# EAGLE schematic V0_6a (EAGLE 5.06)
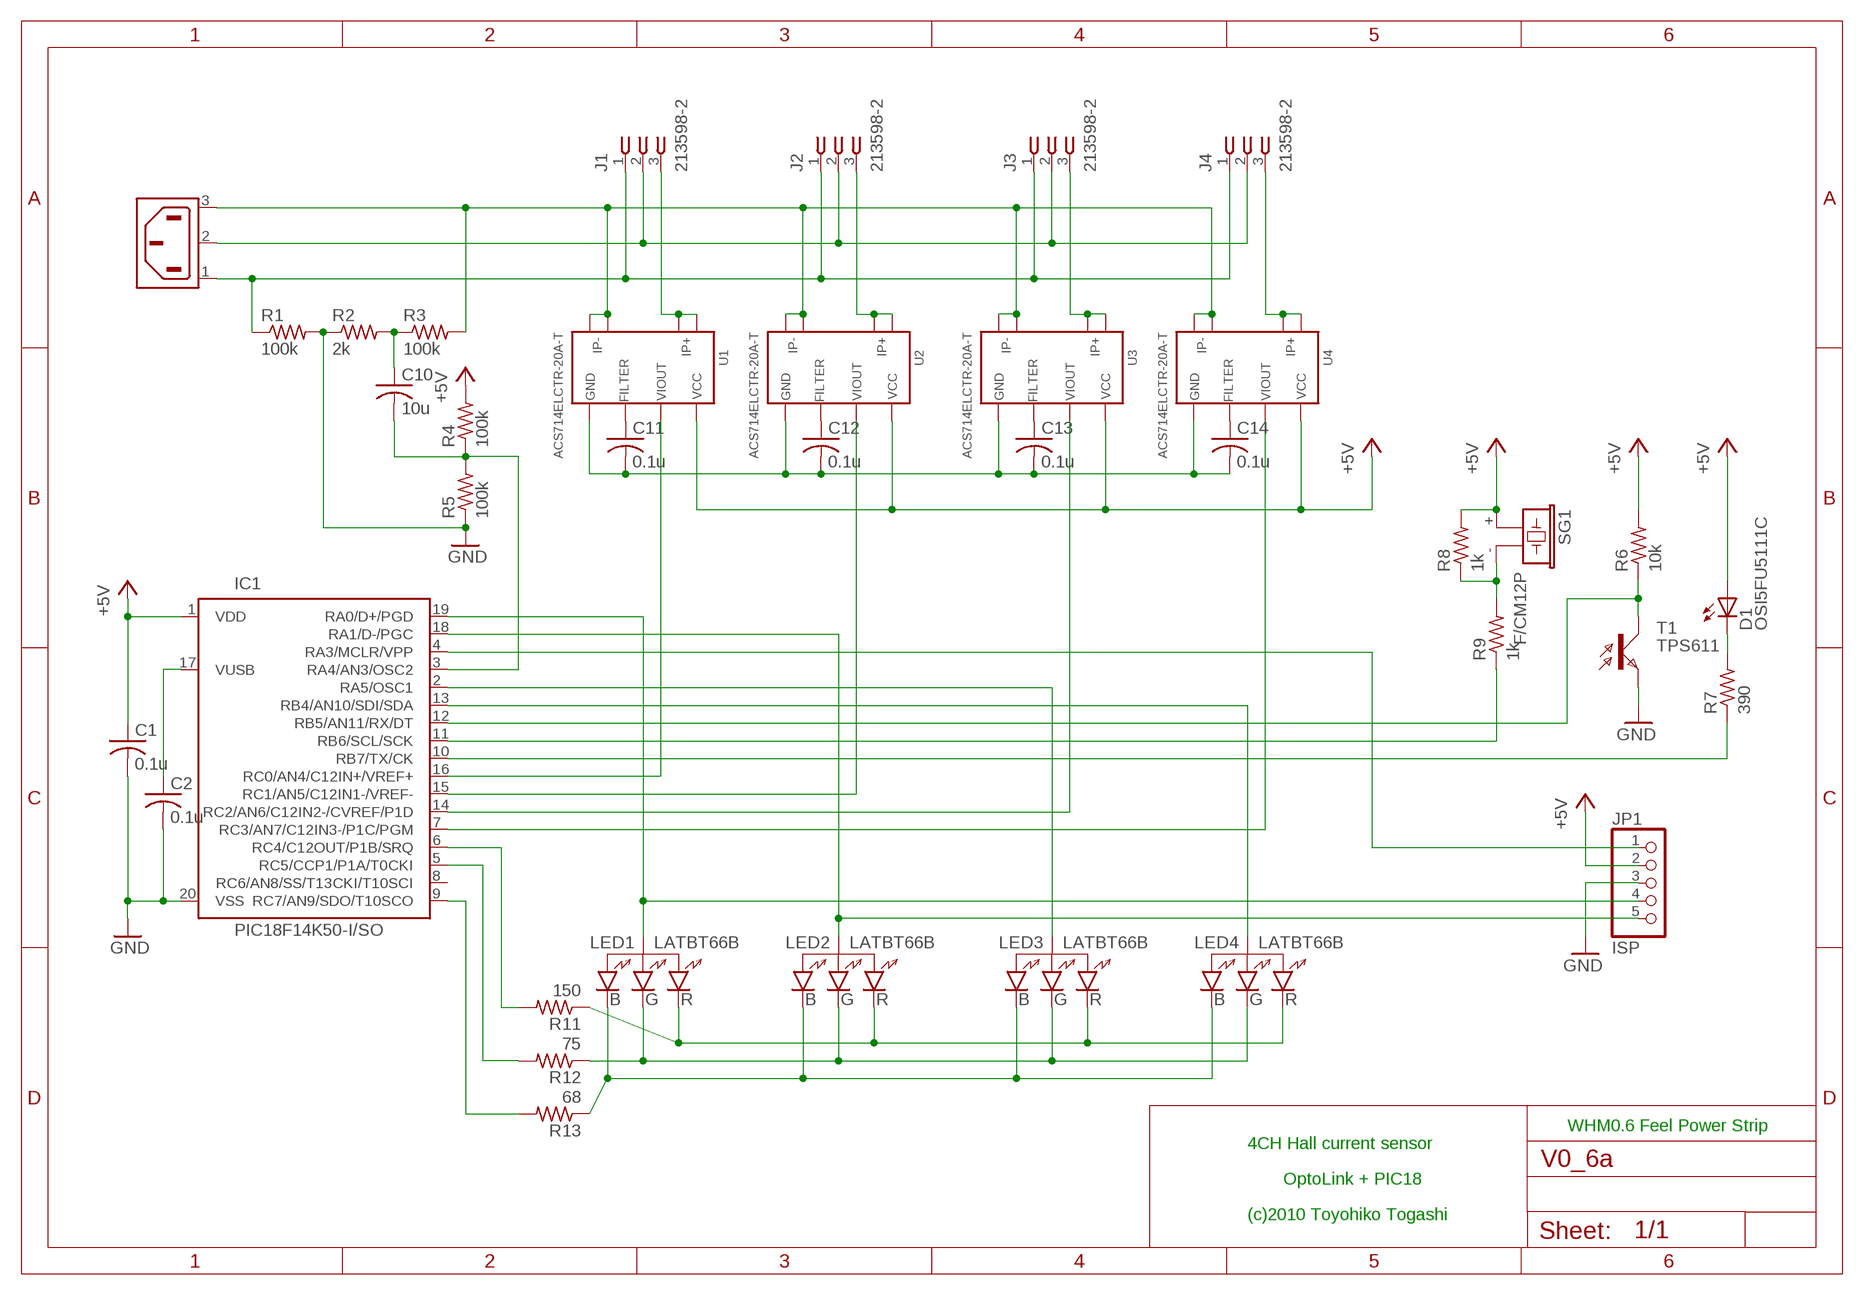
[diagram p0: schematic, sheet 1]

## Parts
C1  0.1u  C-USC0603  [C0603]
C2  0.1u  C-USC0603  [C0603]
C10  10u  C-USC1206  [C1206]
C11  0.1u  C-USC0603  [C0603]
C12  0.1u  C-USC0603  [C0603]
C13  0.1u  C-USC0603  [C0603]
C14  0.1u  C-USC0603  [C0603]
D1  OSI5FU5111C  SFH482  [SFH482]
IC1  PIC18F14K50-I/SO  [SOIC20]
J1  213598-2  [213598-2]
J2  213598-2  [213598-2]
J3  213598-2  [213598-2]
J4  213598-2  [213598-2]
JP1  ISP  PINHD-1X5  [1X05]
LED1  LATBT66B  [P-LCC-4]
LED2  LATBT66B  [P-LCC-4]
LED3  LATBT66B  [P-LCC-4]
LED4  LATBT66B  [P-LCC-4]
R1  100k  R-US_R0603  [R0603]
R2  2k  R-US_R0603  [R0603]
R3  100k  R-US_R0603  [R0603]
R4  100k  R-US_R0603  [R0603]
R5  100k  R-US_R0603  [R0603]
R6  10k  R-US_R0603  [R0603]
R7  390  R-US_R0603  [R0603]
R8  1k  R-US_R0603  [R0603]
R9  1k  R-US_R0603  [R0603]
R11  150  R-US_R0603  [R0603]
R12  75  R-US_R0603  [R0603]
R13  68  R-US_R0603  [R0603]
SG1  F/CM12P  [F/CM12P]
T1  TPS611  BPX81  [BPX81]
U1  ACS714ELCTR-20A-T  [SOP8]
U2  ACS714ELCTR-20A-T  [SOP8]
U3  ACS714ELCTR-20A-T  [SOP8]
U4  ACS714ELCTR-20A-T  [SOP8]
X1  6ESRM-P  [6ESRM-P]

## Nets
+5V: C1.1 D1.A IC1.1(VDD) JP1.2 R4.2 R6.2 R8.2 SG1.+ U1.P$8(VCC) U2.P$8(VCC) U3.P$8(VCC) U4.P$8(VCC)
GND: C1.2 C2.2 IC1.20(VSS) JP1.3 R1.2 R2.1 R5.1 T1.E
N$1: C10.2 IC1.3(RA4/AN3/OSC2) R4.1 R5.2
N$2: IC1.15(RC1/AN5/C12IN1-/VREF-) U2.P$7(VIOUT)
N$3: IC1.14(RC2/AN6/C12IN2-/CVREF/P1D) U3.P$7(VIOUT)
N$4: IC1.7(RC3/AN7/C12IN3-/P1C/PGM) U4.P$7(VIOUT)
N$5: J1.1 J2.1 J3.1 J4.1 R1.1 X1.1(AC1)
N$6: IC1.16(RC0/AN4/C12IN+/VREF+) U1.P$7(VIOUT)
N$7: C11.2 C12.2 C13.2 C14.2 U1.P$5(GND) U2.P$5(GND) U3.P$5(GND) U4.P$5(GND)
N$8: IC1.6(RC4/C12OUT/P1B/SRQ) R11.2
N$9: IC1.5(RC5/CCP1/P1A/T0CKI) R12.2
N$10: IC1.9(RC7/AN9/SDO/T10SCO) R13.2
N$11: J1.2 J2.2 J3.2 J4.2 X1.2(SH)
N$12: C12.1 U2.P$6(FILTER)
N$13: C11.1 U1.P$6(FILTER)
N$14: C13.1 U3.P$6(FILTER)
N$15: IC1.19(RA0/D+/PGD) JP1.4 LED1.P$2
N$16: C14.1 U4.P$6(FILTER)
N$17: R3.2 U1.P$3(IP-1) U1.P$4(IP-2) U2.P$3(IP-1) U2.P$4(IP-2) U3.P$3(IP-1) U3.P$4(IP-2) U4.P$3(IP-1) U4.P$4(IP-2) X1.3(AC2)
N$18: J2.3 U2.P$1(IP+1) U2.P$2(IP+2)
N$19: J3.3 U3.P$1(IP+1) U3.P$2(IP+2)
N$20: J4.3 U4.P$1(IP+1) U4.P$2(IP+2)
N$21: IC1.11(RB6/SCL/SCK) R9.1
N$22: J1.3 U1.P$1(IP+1) U1.P$2(IP+2)
N$23: IC1.18(RA1/D-/PGC) JP1.5 LED2.P$2
N$24: IC1.2(RA5/OSC1) LED3.P$2
N$25: IC1.13(RB4/AN10/SDI/SDA) LED4.P$2
N$26: R8.1 R9.2 SG1.-
N$27: D1.K(C) R7.2
N$28: LED1.P$1 LED2.P$1 LED3.P$1 LED4.P$1 R11.1
N$29: IC1.10(RB7/TX/CK) R7.1
N$30: LED1.P$4 LED2.P$4 LED3.P$4 LED4.P$4 R12.1
N$31: LED1.P$3 LED2.P$3 LED3.P$3 LED4.P$3 R13.1
N$32: IC1.4(RA3/MCLR/VPP) JP1.1
N$33: C2.1 IC1.17(VUSB)
N$34: IC1.12(RB5/AN11/RX/DT) R6.1 T1.C
N$48: C10.1 R2.2 R3.1
Unconnected: IC1.8(RC6/AN8/SS/T13CKI/T10SCI)

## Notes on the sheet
- WHM0.6 Feel Power Strip
- 4CH Hall current sensor
- OptoLink + PIC18
- (c)2010 Toyohiko Togashi

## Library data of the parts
C1 C2 C10-C14 = rcl:C-US: CAPACITOR, American symbol
D1 = led:SFH482: IR LED
IC1 = TOG:PIC18F14K50
J1-J4 = con-amp:213598-2: AC Jack Source: ENG_CD_213598_M.pdf
JP1 = pinhead:PINHD-1X5: PIN HEADER
LED1-LED4 = TOG:LATBT66B: RGB LED SMD
R1-R9 R11-R13 = rcl:R-US_: RESISTOR, American symbol
SG1 = buzzer:F/CM12P: BUZZER
T1 = opto-trans-siemens:BPX81: PHOTO TRANSISTOR
U1-U4 = TOG:ACS714
X1 = con-tycoelectronics:6ESRM-P: AC Connector 120/250 VAC Source: http://catalog.tycoelectronics.com .. ENG_DS_1654001_1099_SR_0406.pdf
